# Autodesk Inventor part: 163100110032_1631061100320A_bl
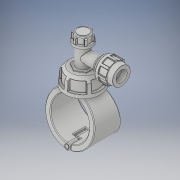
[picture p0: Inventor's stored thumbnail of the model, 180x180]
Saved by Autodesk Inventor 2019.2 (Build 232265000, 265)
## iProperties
Created: 2022-02
Part Number: 163100110032_1631061100320A_bl
Material: Generic
Description: Plassadle Tapper 110x32
Document SubType Name: Modeling
Designer: comp2
Density: 1 g/cm^3
Appearance: Default
Author: comp2
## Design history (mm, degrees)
derived "16310.ipt"
feature "Solid1::16310.ipt" dims "ScaleForDerivedMember" = 10
feature "Solid2::16310.ipt" dims "ScaleForDerivedMember" = 10
feature "Solid3::16310.ipt" dims "ScaleForDerivedMember" = 10
feature "Solid4::16310.ipt" dims "ScaleForDerivedMember" = 10
tag "TaggingFeature1"
body "Solid1"
body "Solid2"
body "Solid3"
body "Solid4"
other parameters: "d1" = 32 [user parameter], "B" = 141 [user parameter], "L" = 97 [user parameter], "E_" = 64 [user parameter], "E1" = 102 [user parameter], "H1" = 273 [user parameter], "H2" = 144 [user parameter], "H3" = 111 [user parameter], "H_costum" = 49 [user parameter], "d2" = 141 [user parameter], "d3" = 55 [user parameter], "d5" = 273 [user parameter], "d7" = 133.95 [user parameter], "d8" = 85 deg [user parameter], "d9" = 45 deg [user parameter], "d10" = 102 [user parameter], "d11" = 49 [user parameter], "d12" = 34.3 [user parameter], "d13" = 35.7 [user parameter], "d14" = 55.08 [user parameter], "d15" = 2.45 [user parameter], "d16" = 2 [user parameter], "d17" = 2 [user parameter], "d18" = 29.4 [user parameter], "d19" = 7.35 [user parameter], "d20" = 1 [user parameter], "d21" = 30.6 [user parameter], "d22" = 1 [user parameter], "d23" = 14.7 [user parameter], "d24" = 111 [user parameter], "d27" = 144 [user parameter], "d29" = 64 [user parameter], "d31" = 51.2 [user parameter], "d32" = 44.4 [user parameter], "d33" = 15.54 [user parameter], "d34" = 93 deg [user parameter], "d35" = 2 [user parameter], "d36" = 4 [user parameter], "d39" = 45 deg [user parameter], "d40" = 4 [user parameter], "d41" = 5 [user parameter], "d42" = 3.1 [user parameter], "d46" = 51 [user parameter], "d47" = 32 [user parameter], "d48" = 49 [user parameter], "d49" = 2.82 [user parameter], "d50" = 97 [user parameter], "d51" = 0 [user parameter], "d52" = 21.7 [user parameter], "d53" = 77.55 [user parameter], "d54" = 33.95 [user parameter], "d55" = 0 [user parameter], "d56" = 19.4 [user parameter], "d57" = 19.4 [user parameter], "d59" = 0 [user parameter], "d60" = 97 [user parameter], "d61" = 0 [user parameter], "d62" = 33.95 [user parameter], "d63" = 0 [user parameter], "d65" = 0 [user parameter], "d67" = 0 [user parameter], "d69" = 0 [user parameter], "d70" = 1 [user parameter], "d71" = 93.12 [user parameter], "d72" = 0 [user parameter], "d73" = 2 [user parameter], "d77" = 32 [user parameter], "d78" = 86.7 [user parameter], "d79" = 5.1 [user parameter], "d80" = 60 deg [user parameter], "d81" = 5.1 [user parameter], "d84" = 0 [user parameter], "d85" = 1 [user parameter], "d87" = 360 deg [user parameter], "d90" = 0 [user parameter], "d91" = 1 [user parameter], "d93" = 60 deg [user parameter], "d94" = 3.06 [user parameter], "d95" = 3.06 [user parameter], "d97" = 0 [user parameter], "d98" = 0.5 [user parameter], "d100" = 360 deg [user parameter], "d102" = 2 [user parameter], "d105" = 0 [user parameter], "d106" = 45 deg [user parameter], "d107" = 3.2 [user parameter], "d108" = 3.2 [user parameter], "d109" = 2.95332 [user parameter], "d110" = -8 [user parameter], "d112" = 0 [user parameter], "d113" = 0.5 [user parameter], "d115" = 360 deg [user parameter], "d117" = 0.5 [user parameter]
